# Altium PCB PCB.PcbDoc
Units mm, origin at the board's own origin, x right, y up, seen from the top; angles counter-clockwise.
Board outline 80 x 20 mm, 2 copper layers (Top Layer, Bottom Layer), stack 1.569 mm thick; 6 components, 5 nets, 17 pads, 14 vias.
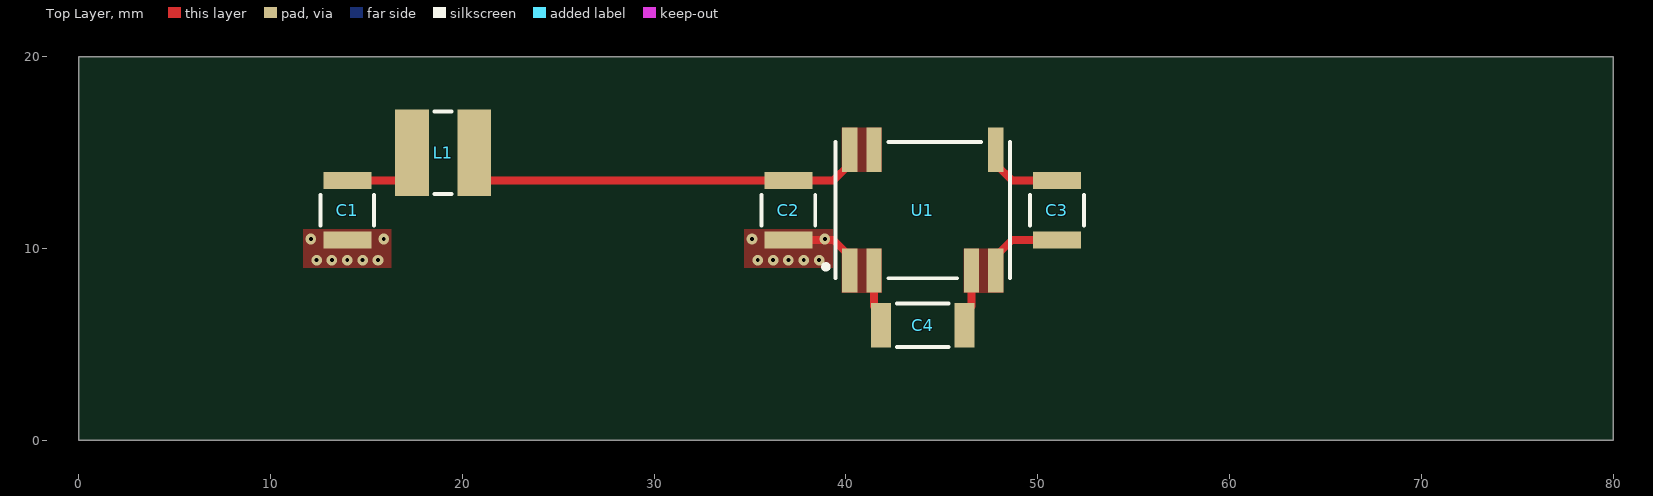
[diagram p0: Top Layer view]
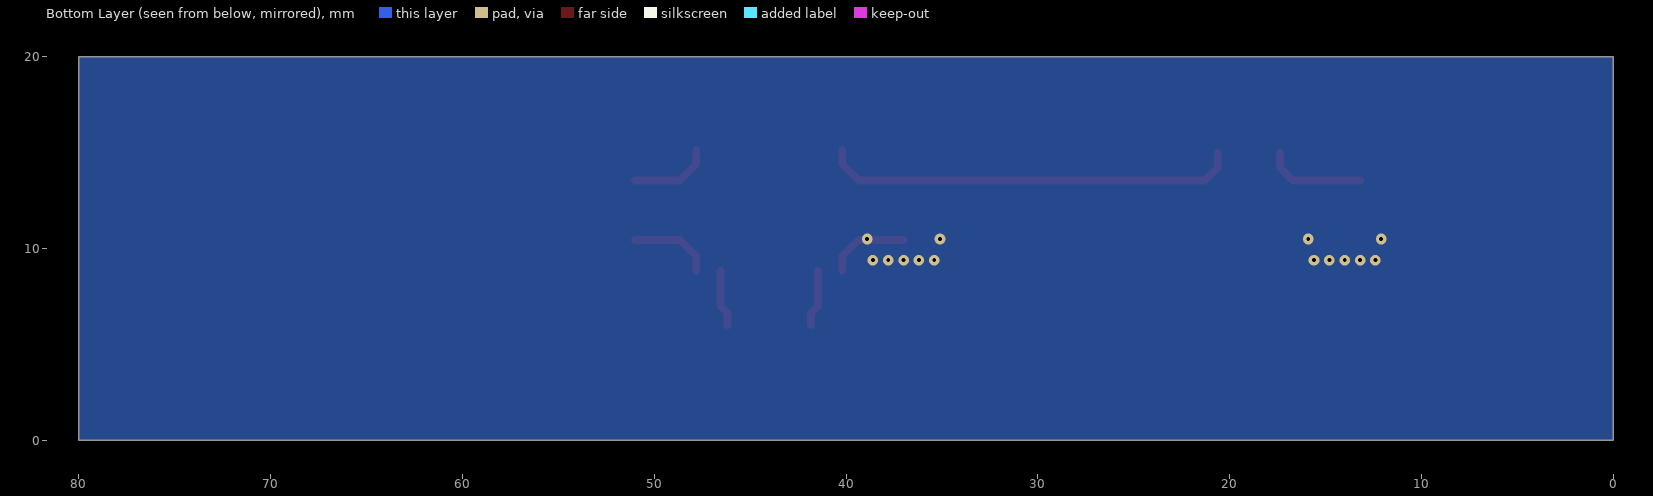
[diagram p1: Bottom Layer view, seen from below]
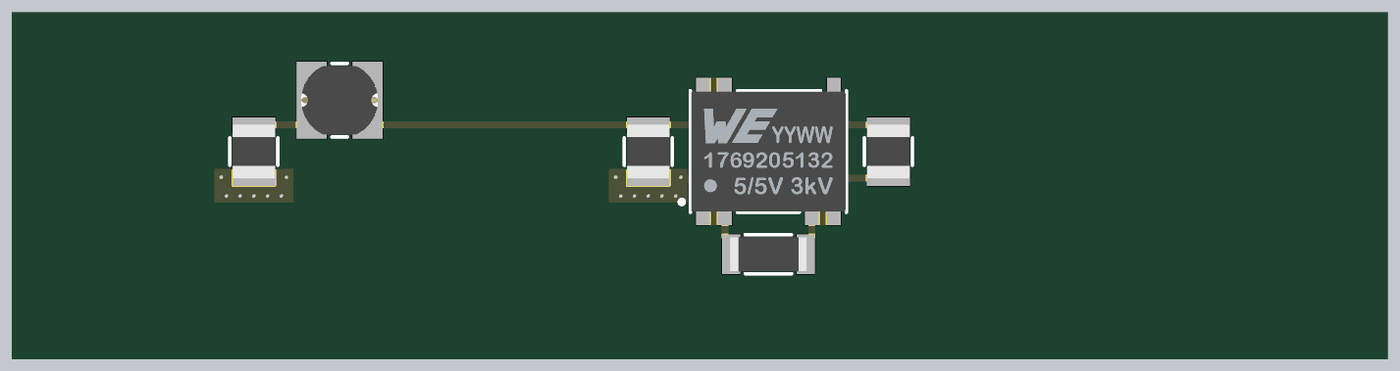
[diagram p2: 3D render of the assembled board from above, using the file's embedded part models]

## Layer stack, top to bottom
Top Solder: solder mask 0.0254, SM-001, Dk 4
Top Layer: signal copper 0.035
Dielectric 1: core 1.4986, Core-043, Dk 4.3
Bottom Layer: signal copper 0.035
Bottom Solder: solder mask 0.0254, SM-001, Dk 4

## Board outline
0,0 80,0 80,20 0,20

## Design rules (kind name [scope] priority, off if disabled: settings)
Clearance [All] p1: gap=0.25 ignorepadtopadclearanceinfootprint=FALSE
HoleSize [All] p1: absolutevalues=TRUE maxlimit=5 minlimit=0.025 maxpercent=80.000 minpercent=20.000
MinimumSolderMaskSliver [All] p1: minsoldermaskwidth=0.07
PolygonConnect [All] p1: connectstyle=Direct reliefconductorwidth=0.254 reliefentries=4 polygonreliefangle="90 Angle" airgapwidth=0.254
RoutingVias [All] p1: holewidth=0.2 width=0.55 viastyle="Through Hole" minholewidth=0.2 minwidth=0.55 maxholewidth=1 maxwidth=1.35
SilkToSilkClearance [All] p1: silktosilkclearance=0.1
SilkToSolderMaskClearance [IsPad] p1: minsilkscreentomaskgap=0.1 clearancetoexposedcopper=TRUE
SolderMaskExpansion [All] p1: expansion=0.06 istentingtop=FALSE
Width [All] p1: maxlimit=2 minlimit=0.25 preferedwidth=0.4 minimp=50.000000 maximp=50.000000 favimp=50.000000
26 further rules are at their usual default settings.

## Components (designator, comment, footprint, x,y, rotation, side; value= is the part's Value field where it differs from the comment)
C1 "885012209027" WCAP-CSGP_1210_H=2mm 14,12 r90 top
C2 "885012209027" WCAP-CSGP_1210_H=2mm 37,12 r90 top
C3 "885012209014" WCAP-CSGP_1210_H=2mm 51,12 r90 top
C4 "885342210004" WCAP-CSMH_1808_H2 44,6 r0 top value=1nF
L1 "744773068" WE-PD2_4532 19,15 r0 top
U1 "1769205132" WPME-FIMM_LGA-7_L9W7H3.1 44,12 r0 top

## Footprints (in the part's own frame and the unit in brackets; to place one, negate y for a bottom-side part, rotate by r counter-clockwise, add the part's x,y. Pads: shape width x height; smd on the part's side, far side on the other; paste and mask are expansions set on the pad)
WCAP-CSGP_1210_H=2mm [mm] "Ceramic Capacitors, body 3.2x2.5mm"
  rect 0.9x2.5 smd: 1(-1.55,0) 2(1.55,0)
  silkscreen extent -0.8,-1.4 0.8,1.4, body extent -1.6,-1.25 1.6,1.25, height 2
WCAP-CSMH_1808_H2 [mm] "Ceramic Capacitors, body 4.5x2.03mm"
  rect 1.05x2.3 smd: 1(-2.175,0) 2(2.175,0)
  silkscreen extent -1.35,-1.14 1.35,1.14, body extent -2.25,-1.01 2.25,1.02, height 2
WE-PD2_4532 [mm] "SMD Power Inductor, 2-Leads, body 4x4.5mm"
  rect 1.75x4.5 smd: 1(-1.625,0) 2(1.625,0)
  silkscreen extent -0.45,-2.15 0.45,2.15, body extent -2.25,-2 2.25,2, height 3.22
WPME-FIMM_LGA-7_L9W7H3.1 [mm] "Power Module, SMT, body 9.00x7.00mm"
  rect 0.8x2.3 smd: 1(-3.81,-3.15) 2(-2.54,-3.15) 3(2.54,-3.15) 4(3.81,-3.15) 5(3.81,3.15) 6(-2.54,3.15) 7(-3.81,3.15)
  silkscreen extent -5.17,-3.55 4.55,3.55, body extent -4.5,-3.5 4.5,3.5, height 3.1

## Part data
C1 C2: library part CMP-051-000886-10, "WCAP-CSGP Multilayer Ceramic Chip Capacitor, General Purpose, size 1210, X7R, 4.7uF, 25V", Capacitance=4.7uF, Capacitance Tolerance=+/-10%, Isolation Resistance=>{}0.1GOhm, Operating Temperature="-55 to +125degC", Rated Voltage=25VDC
C3: library part CMP-051-000873-10, "WCAP-CSGP Multilayer Ceramic Chip Capacitor, General Purpose, size 1210, X7R, 10uF, 16V", Capacitance=10uF, Capacitance Tolerance=+/-10%, Isolation Resistance=>{}0.1GOhm, Operating Temperature="-55 to +125degC", Rated Voltage=16VDC
C4: library part CMP-055-000091-5, "WCAP-CSMH Multilayer Ceramic Chip Capacitor, size 1808, X7R Class II, 1nF, 3000V", Capacitance Tolerance=+/-10%, Insulation Resistance=10GOhm, Operating Temperature="-55 to +125degC", Rated Voltage=3000VDC
L1: library part CMP-495-000010-A.4, "WE-PD2 SMT Power Inductor, size 4532, 6.8uH, 1.54A", DC Resistance max.=0.131Ohm, DC Resistance typ.=0.076Ohm, Inductance=6.8uH, Manufacturer="Wurth Elektronik", Operating Temperature="-40 to +125degC", Rated Current=1.54A, Saturation Current=2.1A, Self Resonant Frequency=41MHz
U1: library part CMP-IC-00008-A.1, "WPME-FIMM Fixed Isolated Module, LGA-7, 4.5-5.5Vin, 5Vout", Case/Size Code=LGA-7, Input Voltage=5V, Input Voltage max=5.5V, Input Voltage min=4.5V, Isolation Voltage=3kV, Manufacturer="Wurth Elektronik", Operating Temperature max=105°C, Operating Temperature min=-40°C

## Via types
v1: diameter 0.55, hole 0.2, Top Layer to Bottom Layer, tented both sides, 14 vias

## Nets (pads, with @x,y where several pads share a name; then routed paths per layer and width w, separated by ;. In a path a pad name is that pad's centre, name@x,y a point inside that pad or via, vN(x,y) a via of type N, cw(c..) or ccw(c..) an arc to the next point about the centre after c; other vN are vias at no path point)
NetC2_2: C2.2 L1.2 U1.6 U1.7 | length 21.7
  Top Layer w0.4: L1.2 20.625,14.225 21.3,13.55 C2.2 39.34,13.55 40.19,14.4 U1.7
VIN: C1.2 L1.1 | length 5.2
  Top Layer w0.4: C1.2@13.2,13.55 C1.2 16.7,13.55 17.375,14.225 L1.1
VINGND: C1.1 C2.1 C4.1 U1.1 U1.2 | length 7.3
  Top Layer w0.4: C2.1 39.34,10.45 40.19,9.6 U1.1 ; U1.2 41.46,6.99 41.825,6.625 C4.1
  other v1: 12.4,9.4 13.2,9.4 14,9.4 14.8,9.4 15.6,9.4 35.4,9.4 36.2,9.4 37,9.4 37.8,9.4 38.6,9.4 12.1,10.5 15.9,10.5 35.1,10.5 38.9,10.5
VOUT: C3.2 U1.5 | length 4.3
  Top Layer w0.4: U1.5 47.81,14.4 48.66,13.55 C3.2
VOUTGND: C3.1 C4.2 U1.3 U1.4 | length 7.3
  Top Layer w0.4: C4.2 46.175,6.625 46.54,6.99 U1.3 ; U1.4 47.81,9.6 48.66,10.45 C3.1

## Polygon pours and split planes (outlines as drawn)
VINGND on Bottom Layer "VINGND_L02_P000" (solid, remove dead copper, pour order 0): 0,0 0,20 80,20 80,0
VINGND on Top Layer "VINGND_L01_P050" (solid, pour order 50): 34.7,11 34.7,9 39.3,9 39.3,11
VINGND on Top Layer "VINGND_L01_P049" (solid, pour order 49): 11.7,11 11.7,9 16.3,9 16.3,11
NetC2_2 on Top Layer "NETC2_2_L01_P048" (solid, pour order 48): 39.79,16.3 39.79,14 41.86,14 41.86,16.3
VINGND on Top Layer "VINGND_L01_P047" (solid, pour order 47): 39.79,10 39.79,7.7 41.86,7.7 41.86,10
VOUTGND on Top Layer "VOUTGND_L01_P046" (solid, pour order 46): 46.14,10 46.14,7.7 48.21,7.7 48.21,10

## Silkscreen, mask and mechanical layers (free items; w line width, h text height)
Board:
  the board outline again, w0.254
Datasheet Outline (Mech18):
  lines w0.254: 12.4,9.8 15.6,9.8 15.6,14.2 12.4,14.2 12.4,9.8 ; 16.3,12.55 21.7,12.55 21.7,17.45 16.3,17.45 16.3,12.55 ; 35.4,9.8 38.6,9.8 38.6,14.2 35.4,14.2 35.4,9.8 ; 38.975,7.425 49.025,7.425 49.025,16.575 38.975,16.575 38.975,7.425 ; 41.1,4.65 46.9,4.65 46.9,7.35 41.1,7.35 41.1,4.65 ; 49.4,9.8 52.6,9.8 52.6,14.2 49.4,14.2 49.4,9.8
